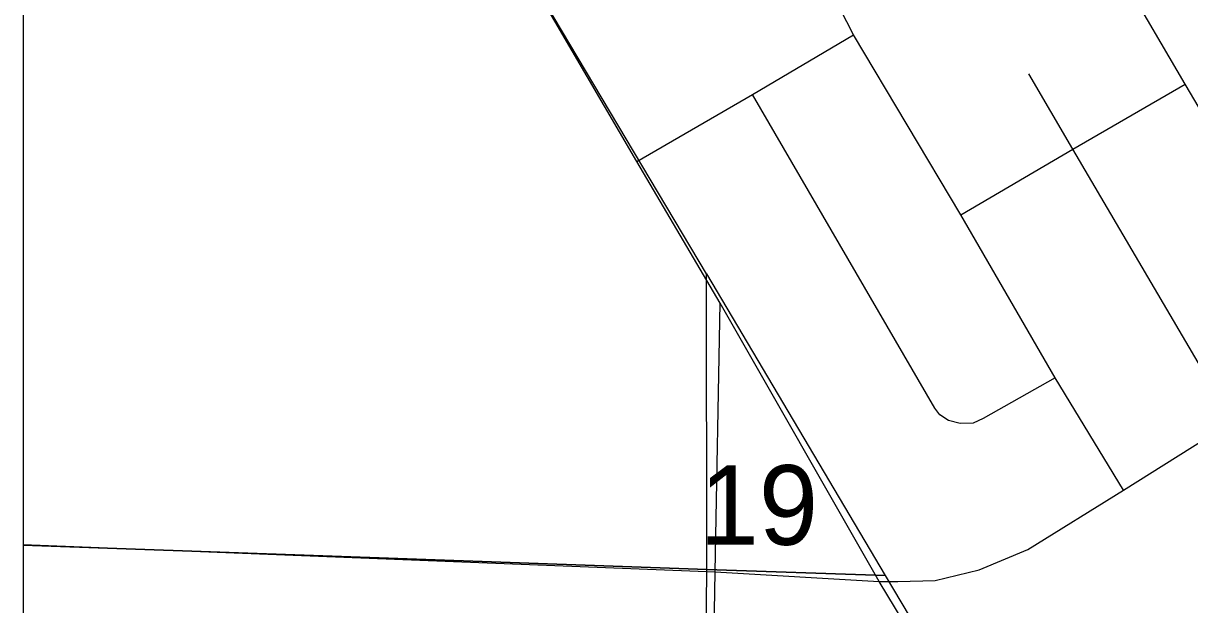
# Model space of a CAD drawing. Extents: x 0 to 34, y 0 to 22.
# Drawn here: x 2.1 to 2.713, y 19.935 to 20.24 of the extents above; entities that cross this region are included whole.
import ezdxf

# ---------------------------------------------------------------- set-up
doc = ezdxf.new("R2010")
doc.units = 0
for name, color, linetype in [('GM_X_City_Street', 7, 'Continuous'), ('GM_X_Corporation', 7, 'Continuous'), ('GM_X_County_Road', 7, 'Continuous'), ('GM_X_Section_Text', 7, 'Continuous'), ('SH_Data', 7, 'Continuous')]:
    doc.layers.add(name, color=color, linetype=linetype)

msp = doc.modelspace()

# ---------------------------------------------------------------- linework, layer by layer
at = {"layer": 'GM_X_City_Street'}
for points in [[(3.23282, 19.54223), (3.10298, 19.59102), (3.09997, 19.59215), (3.08381, 19.59991), (3.06842, 19.60917), (3.04088, 19.64968), (3.01847, 19.6872), (2.98041, 19.7509), (2.94845, 19.8044), (2.91863, 19.85593), (2.88574, 19.9126), (2.79452, 20.06608), (2.71052, 20.20831), (2.64568, 20.31917), (2.61283, 20.37484), (2.54592, 20.48861), (2.46687, 20.61875), (2.45699, 20.63682), (2.30114, 20.9)], [(2.67809, 19.99484), (2.64212, 20.05397), (2.59261, 20.13971), (2.53617, 20.23418), (2.49836, 20.30811), (2.43454, 20.41473), (2.40133, 20.47032), (2.38333, 20.50166), (2.38526, 20.50342), (2.38583, 20.50569), (2.38566, 20.5083), (2.38514, 20.5104), (2.38208, 20.51245), (2.37862, 20.51267), (2.37623, 20.51108), (2.37481, 20.50842), (2.37498, 20.50575), (2.3764, 20.50314), (2.37958, 20.50126), (2.38248, 20.50143)], [(2.42239, 20.16773), (2.48303, 20.20295), (2.53617, 20.23418)], [(2.73556, 20.03105), (2.65144, 20.1741), (2.62829, 20.21379)], [(2.59261, 20.13971), (2.65144, 20.1741), (2.71052, 20.20831)], [(2.64212, 20.05397), (2.6043, 20.03251), (2.59908, 20.03013), (2.59227, 20.03001), (2.58614, 20.0316), (2.58159, 20.03455), (2.57898, 20.03807), (2.48303, 20.20295)]]:
    msp.add_lwpolyline(points, dxfattribs=at)
at = {"layer": 'GM_X_Corporation'}
for points in [[(5.89055, 20.9), (2.1, 20.9), (2.1, 17.32132)], [(5.89055, 20.9), (2.1, 20.9), (2.1, 19.74565), (2.25069, 19.73684), (2.37637, 19.73066), (2.45567, 19.72568), (2.50624, 19.7267), (2.5842, 19.72189), (2.633, 19.7167), (2.66551, 19.71134), (2.69297, 19.70484), (2.74935, 19.69315)], [(5.89055, 20.9), (2.1, 20.9), (2.1, 19.74789), (2.45935, 19.72872), (2.58641, 19.72327), (2.69411, 19.70659), (2.73667, 19.69862)]]:
    msp.add_lwpolyline(points, dxfattribs=at)
for points in [[(2.1, 20.71238), (2.1, 19.96594), (2.45917, 19.95322), (2.45894, 20.10861)], [(2.45894, 20.10861), (2.55283, 19.95009), (2.45917, 19.95322)], [(2.1, 19.96594), (2.1, 18.95617), (2.44896, 18.94331), (2.45445, 19.44844), (2.45917, 19.95322)], [(2.45917, 19.95322), (2.55283, 19.95009), (2.85682, 19.43899), (2.64304, 19.44401), (2.45445, 19.44844)]]:
    msp.add_lwpolyline(points, close=True, dxfattribs=at)
at = {"layer": 'GM_X_County_Road'}
for p, q in [((2.46347, 19.952), (2.4661, 20.09323)), ((2.45974, 19.73736), (2.46347, 19.952))]:
    msp.add_line(p, q, dxfattribs=at)
for points in [[(2.55954, 19.94697), (2.57905, 19.94734), (2.60219, 19.95298), (2.62786, 19.96368), (2.67809, 19.99484), (2.73556, 20.03105), (2.79452, 20.06608), (2.84242, 20.0955), (3.12407, 20.26601), (3.24943, 20.34463), (3.36133, 20.41713), (3.41728, 20.45145), (3.50909, 20.50608)], [(2.54966, 19.94688), (2.4661, 20.09323), (2.42239, 20.16773), (2.34531, 20.29985), (2.2884, 20.39617)], [(2.1, 19.96641), (2.46347, 19.952), (2.54966, 19.94688), (2.55954, 19.94697)], [(2.68335, 19.72504), (2.67586, 19.738), (2.54966, 19.94688)]]:
    msp.add_lwpolyline(points, dxfattribs=at)
at = {"layer": 'SH_Data'}
msp.add_line((2.1, 20.9), (2.1, 14.1), dxfattribs=at)
msp.add_line((2.1, 20.9), (2.1, 14.1), dxfattribs=at)

# ---------------------------------------------------------------- texts
at = {"layer": 'GM_X_Section_Text'}
msp.add_text('19', height=0.041856, rotation=0.00001, dxfattribs=at).set_placement((2.45532, 19.96617))

doc.saveas('drawing.dxf')
